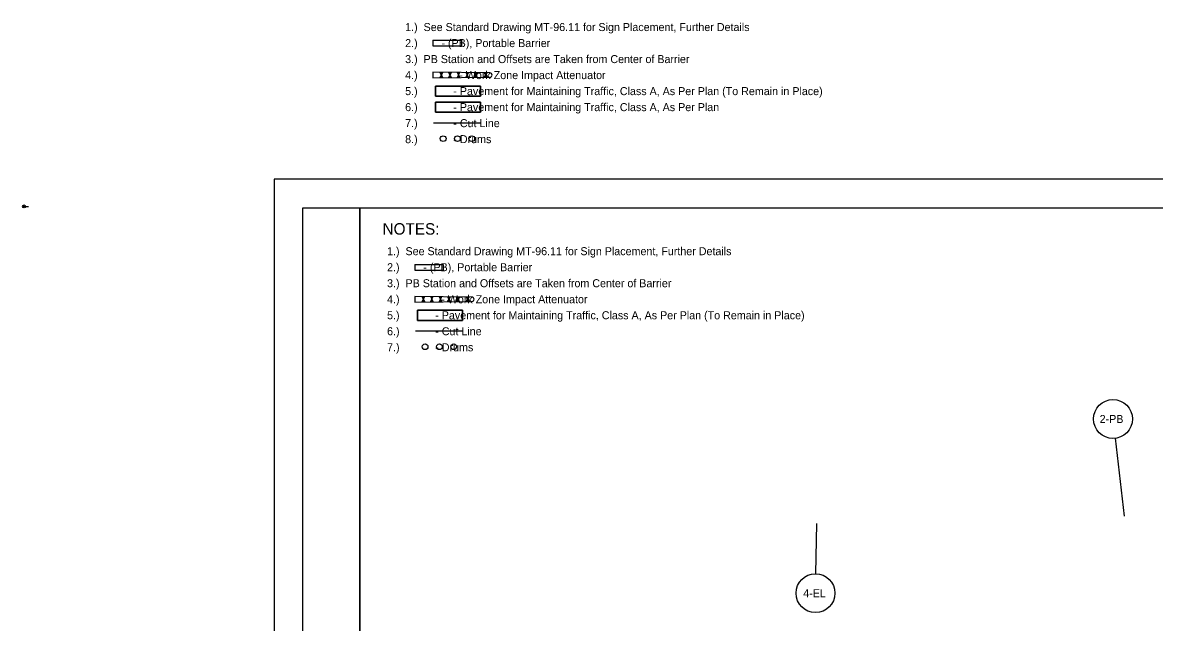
# Model space of a CAD drawing. Extents: x -8.7 to 76.9, y -12.1 to 38.2.
# Drawn here: x -4.4 to 15.4, y 14.25 to 24.74 of the extents above; entities that cross this region are included whole.
import ezdxf

# ---------------------------------------------------------------- set-up
doc = ezdxf.new("R2010")
doc.units = 0
for name, color, linetype in [('Default', 7, 'Continuous'), ('DR_P_Drive_Pipe', 7, 'Continuous'), ('GE_P_CL_20', 7, 'Continuous'), ('MT_P_Drums', 7, 'Continuous'), ('MT_P_Traffic_Attenuator', 7, 'Continuous'), ('MT_X_Temp_Road', 7, 'Continuous'), ('SH_Border', 7, 'Continuous'), ('SH_Cut_Line', 7, 'Continuous'), ('TX_P_20', 7, 'Continuous'), ('TX_X_10', 7, 'Continuous')]:
    doc.layers.add(name, color=color, linetype=linetype)

msp = doc.modelspace()

# ---------------------------------------------------------------- linework, layer by layer
at = {"layer": 'Default'}
for p, q in [((-4.4, 21.526), (-4.348, 21.526)), ((-4.374, 21.526), (-4.3, 21.526))]:
    msp.add_line(p, q, dxfattribs=at)
msp.add_circle((-4.374, 21.526), 0.026, dxfattribs=at)
at = {"layer": 'DR_P_Drive_Pipe'}
for p, q in [((2.775, 24.432), (3.275, 24.432)), ((2.775, 24.432), (2.775, 24.332)), ((3.275, 24.432), (3.275, 24.332)), ((2.775, 24.332), (3.275, 24.332)), ((2.459, 20.513), (2.959, 20.513)), ((2.459, 20.513), (2.459, 20.413)), ((2.459, 20.413), (2.959, 20.413)), ((2.959, 20.513), (2.959, 20.413))]:
    msp.add_line(p, q, dxfattribs=at)
at = {"layer": 'GE_P_CL_20'}
for p, q in [((3.61, 22.982), (2.789, 22.982)), ((3.294, 19.343), (2.473, 19.343))]:
    msp.add_line(p, q, dxfattribs=at)
at = {"layer": 'MT_P_Drums'}
for centre in [(2.956, 22.711), (3.206, 22.711), (3.456, 22.711), (2.64, 19.072), (2.89, 19.072), (3.14, 19.072)]:
    msp.add_circle(centre, 0.05, dxfattribs=at)
at = {"layer": 'MT_P_Traffic_Attenuator'}
for p, q in [((2.775, 23.872), (2.775, 23.772)), ((3.775, 23.859), (2.775, 23.872)), ((2.775, 23.772), (3.775, 23.784)), ((2.9, 23.773), (2.95, 23.87)), ((2.9, 23.87), (2.95, 23.774)), ((2.925, 23.87), (2.925, 23.774)), ((3.05, 23.775), (3.1, 23.868)), ((3.05, 23.868), (3.1, 23.776)), ((3.075, 23.868), (3.075, 23.776)), ((3.2, 23.867), (3.25, 23.778)), ((3.2, 23.777), (3.25, 23.866)), ((3.225, 23.866), (3.225, 23.777)), ((3.35, 23.865), (3.4, 23.78)), ((3.35, 23.779), (3.4, 23.864)), ((3.375, 23.864), (3.375, 23.779)), ((3.5, 23.863), (3.55, 23.782)), ((3.5, 23.781), (3.55, 23.862)), ((3.525, 23.863), (3.525, 23.781)), ((3.675, 23.861), (3.725, 23.784)), ((3.675, 23.783), (3.725, 23.86)), ((3.7, 23.86), (3.7, 23.783)), ((2.459, 19.953), (2.459, 19.853)), ((3.459, 19.94), (2.459, 19.953)), ((2.459, 19.853), (3.459, 19.865)), ((2.584, 19.951), (2.634, 19.855)), ((2.584, 19.854), (2.634, 19.95)), ((2.609, 19.951), (2.609, 19.854)), ((2.734, 19.856), (2.784, 19.949)), ((2.734, 19.949), (2.784, 19.857)), ((2.759, 19.949), (2.759, 19.856)), ((2.884, 19.858), (2.934, 19.947)), ((2.884, 19.947), (2.934, 19.859)), ((2.909, 19.947), (2.909, 19.858)), ((3.034, 19.86), (3.084, 19.945)), ((3.034, 19.945), (3.084, 19.86)), ((3.059, 19.945), (3.059, 19.86)), ((3.184, 19.944), (3.234, 19.862)), ((3.184, 19.862), (3.234, 19.943)), ((3.209, 19.943), (3.209, 19.862)), ((3.359, 19.941), (3.409, 19.864)), ((3.359, 19.864), (3.409, 19.941)), ((3.384, 19.941), (3.384, 19.864))]:
    msp.add_line(p, q, dxfattribs=at)
for centre in [(3.775, 23.822), (3.459, 19.903)]:
    msp.add_arc(centre, 0.0375, 269.9997, 89.9997, dxfattribs=at)
at = {"layer": 'MT_X_Temp_Road'}
for points in [[(2.825, 23.631), (3.61, 23.631), (3.61, 23.453), (2.825, 23.453)], [(2.825, 23.631), (2.825, 23.453), (3.61, 23.453), (3.61, 23.631)], [(2.825, 23.351), (3.61, 23.351), (3.61, 23.173), (2.825, 23.173)], [(2.825, 23.351), (2.825, 23.173), (3.61, 23.173), (3.61, 23.351)], [(2.509, 19.712), (3.294, 19.712), (3.294, 19.534), (2.509, 19.534)], [(2.509, 19.712), (2.509, 19.534), (3.294, 19.534), (3.294, 19.712)]]:
    msp.add_lwpolyline(points, close=True, dxfattribs=at)
at = {"layer": 'SH_Border'}
for points in [[(0.5, 21.5), (1.5, 21.5), (1.5, 0.5), (0.5, 0.5)], [(1.5, 21.5), (33.5, 21.5), (33.5, 0.5), (1.5, 0.5)]]:
    msp.add_lwpolyline(points, close=True, dxfattribs=at)
at = {"layer": 'SH_Cut_Line'}
msp.add_lwpolyline([(0, 0), (34, 0), (34, 22), (0, 22)], close=True, dxfattribs=at)
at = {"layer": 'TX_P_20'}
for p, q in [((14.713, 17.472), (14.87, 16.112)), ((9.475, 15.103), (9.491, 15.981))]:
    msp.add_line(p, q, dxfattribs=at)
at = {"layer": 'TX_X_10'}
for centre in [(14.673, 17.809), (9.469, 14.763)]:
    msp.add_circle(centre, 0.34, dxfattribs=at)

# ---------------------------------------------------------------- texts
at = {"layer": 'Default'}
for s, p in [('Plan 2', (-4.38, 21.516)), ('1', (-4.375, 21.532)), ('CLX_RW_2 - Plan 2', (-4.341, 21.532)), ('1:20', (-4.341, 21.516))]:
    msp.add_text(s, height=0.00328, dxfattribs=at).set_placement(p)
at = {"layer": 'DR_P_Drive_Pipe'}
msp.add_text('NOTES:', height=0.2, dxfattribs=at).set_placement((1.896, 21.033))
for s, p in [('2-PB', (14.44, 17.739)), ('4-EL', (9.255, 14.693))]:
    msp.add_text(s, height=0.14, rotation=360, dxfattribs=at).set_placement(p)
at = {"layer": 'GE_P_CL_20'}
for s, p in [('1.)  See Standard Drawing MT-96.11 for Sign Placement, Further Details', (2.291, 24.592)), ('2.)        - (PB), Portable Barrier', (2.291, 24.312)), ('3.)  PB Station and Offsets are Taken from Center of Barrier', (2.291, 24.032)), ('4.)              - Work Zone Impact Attenuator', (2.291, 23.752)), ('5.)            - Pavement for Maintaining Traffic, Class A, As Per Plan (To Remain in Place)', (2.291, 23.472)), ('6.)            - Pavement for Maintaining Traffic, Class A, As Per Plan', (2.291, 23.192)), ('7.)            - Cut Line', (2.291, 22.912)), ('8.)            - Drums', (2.291, 22.632)), ('1.)  See Standard Drawing MT-96.11 for Sign Placement, Further Details', (1.975, 20.673)), ('2.)        - (PB), Portable Barrier', (1.975, 20.393)), ('3.)  PB Station and Offsets are Taken from Center of Barrier', (1.975, 20.113)), ('4.)              - Work Zone Impact Attenuator', (1.975, 19.833)), ('5.)            - Pavement for Maintaining Traffic, Class A, As Per Plan (To Remain in Place)', (1.975, 19.553)), ('6.)            - Cut Line', (1.975, 19.273)), ('7.)            - Drums', (1.975, 18.993))]:
    msp.add_text(s, height=0.14, dxfattribs=at).set_placement(p)

doc.saveas('drawing.dxf')
